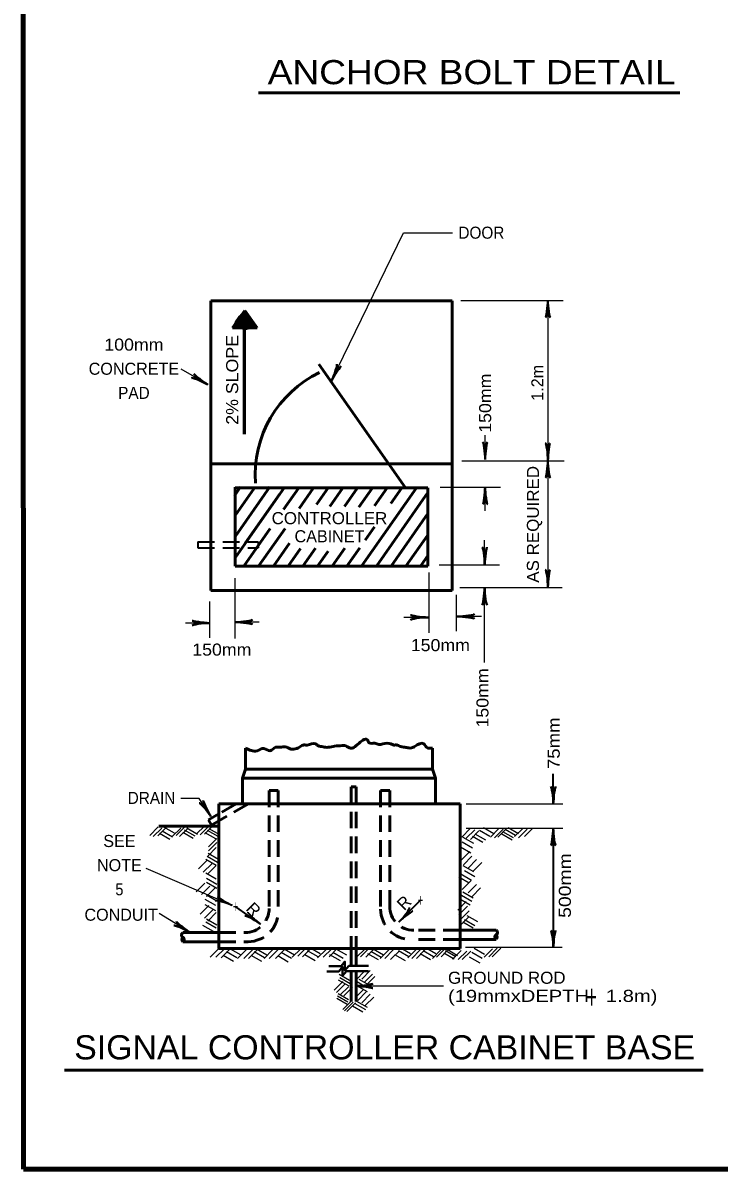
# Model space of a CAD drawing. Extents: x -711 to 145, y 25 to 569.
# Drawn here: x -653.6 to -515, y 36.6 to 264.5 of the extents above; entities that cross this region are included whole.
import ezdxf
from ezdxf.enums import TextEntityAlignment as Align

# ---------------------------------------------------------------- set-up
doc = ezdxf.new("R2010")
doc.units = 0
doc.header["$LTSCALE"] = 1.1
doc.linetypes.add('MEDIUM_DASHED', pattern=[4.5, 3, -1.5])
doc.layers.add('1', color=7, linetype='Continuous', lineweight=53)

msp = doc.modelspace()

# ---------------------------------------------------------------- linework, layer by layer
at = {"layer": '1'}
for p, q in [((-606.714, 250.622), (-522.826, 250.622)), ((-616.166, 209.253), (-616.166, 151.653)), ((-616.166, 209.253), (-609.079, 209.253)), ((-611.365, 209.253), (-611.365, 209.114)), ((-611.223, 209.253), (-568.166, 209.253)), ((-568.166, 209.253), (-568.166, 151.653)), ((-609.428, 207.33), (-611.866, 203.848)), ((-609.428, 207.33), (-606.991, 203.848)), ((-611.866, 203.848), (-606.991, 203.848)), ((-577.468, 172.049), (-594.676, 196.623)), ((-616.166, 176.853), (-568.166, 176.853)), ((-610.281, 172.228), (-611.499, 170.489)), ((-611.365, 172.188), (-611.365, 172.002)), ((-611.365, 172.053), (-611.223, 172.053)), ((-611.365, 172.053), (-572.966, 172.053)), ((-611.365, 172.053), (-611.365, 156.453)), ((-601.614, 172.053), (-611.365, 158.127)), ((-607.618, 171.847), (-611.343, 166.528)), ((-604.417, 172.235), (-611.299, 162.405)), ((-598.684, 172.053), (-601.698, 167.749)), ((-595.755, 172.053), (-598.616, 167.966)), ((-592.825, 172.053), (-595.165, 168.711)), ((-589.895, 172.053), (-592.48, 168.361)), ((-586.965, 172.053), (-589.567, 168.336)), ((-584.035, 172.053), (-586.751, 168.174)), ((-575.245, 172.053), (-586.169, 156.453)), ((-581.105, 172.053), (-583.598, 168.493)), ((-572.966, 171.125), (-583.239, 156.453)), ((-578.175, 172.053), (-580.339, 168.963)), ((-572.966, 172.053), (-572.966, 156.453)), ((-602.451, 170.859), (-609.333, 161.029)), ((-572.966, 166.941), (-580.309, 156.453)), ((-583.594, 164.314), (-585.461, 161.648)), ((-604.353, 163.957), (-609.608, 156.453)), ((-601.416, 163.967), (-606.678, 156.453)), ((-573.095, 162.572), (-577.379, 156.453)), ((-600.545, 161.027), (-603.748, 156.453)), ((-598.33, 160.007), (-600.818, 156.453)), ((-595.364, 160.057), (-597.888, 156.453)), ((-589.53, 160.021), (-592.028, 156.453)), ((-586.556, 160.084), (-589.099, 156.453)), ((-592.837, 159.482), (-594.958, 156.453)), ((-572.966, 158.572), (-574.371, 156.565)), ((-611.365, 156.453), (-572.966, 156.453)), ((-616.166, 151.653), (-568.166, 151.653)), ((-609.272, 116.072), (-609.272, 120.272)), ((-572.072, 116.072), (-572.072, 120.272)), ((-609.272, 116.072), (-609.901, 114.3)), ((-609.901, 114.3), (-571.501, 114.3)), ((-609.901, 114.3), (-609.901, 109.211)), ((-609.272, 116.072), (-572.072, 116.072)), ((-572.072, 116.072), (-571.501, 114.3)), ((-571.501, 114.3), (-571.501, 109.211)), ((-614.59, 107.207), (-616.676, 106.003)), ((-614.59, 109.211), (-566.59, 109.211)), ((-614.59, 109.211), (-614.59, 80.411)), ((-566.59, 109.211), (-566.59, 80.411)), ((-616.676, 106.003), (-616.076, 104.964)), ((-614.59, 105.822), (-616.076, 104.964)), ((-626.547, 104.789), (-614.547, 104.789)), ((-621.737, 83.595), (-614.537, 83.595)), ((-566.618, 84.053), (-559.418, 84.053)), ((-566.618, 82.252), (-559.418, 82.252)), ((-621.737, 81.795), (-614.537, 81.795)), ((-614.59, 80.411), (-566.59, 80.411)), ((-588.238, 80.416), (-588.238, 76.928)), ((-587.265, 80.501), (-587.265, 76.901)), ((-588.238, 75.87), (-588.238, 69.898)), ((-587.278, 75.898), (-587.278, 69.898)), ((-645.301, 56.213), (-518.171, 56.213))]:
    msp.add_line(p, q, dxfattribs=at)
at = {"layer": '1', "lineweight": 25}
for p, q in [((-566.442, 209.315), (-546.042, 209.315)), ((-616.795, 192.577), (-622.077, 195.644)), ((-561.593, 177.704), (-561.593, 182.504)), ((-566.255, 177.424), (-545.855, 177.424)), ((-570.545, 172.203), (-558.545, 172.203)), ((-561.593, 167.447), (-561.593, 172.247)), ((-561.686, 156.817), (-561.686, 161.617)), ((-572.783, 155.232), (-572.783, 143.232)), ((-570.731, 156.724), (-558.731, 156.724)), ((-611.387, 154.113), (-611.387, 142.113)), ((-567.374, 150.756), (-567.374, 143.556)), ((-566.628, 152.248), (-546.228, 152.248)), ((-561.686, 137.311), (-561.686, 152.199)), ((-616.422, 149.45), (-616.422, 142.25)), ((-572.969, 146.28), (-577.769, 146.28)), ((-562.339, 146.466), (-567.139, 146.466)), ((-616.422, 145.161), (-621.222, 145.161)), ((-606.538, 145.347), (-611.338, 145.347)), ((-565.351, 109.2), (-546.151, 109.2)), ((-617.385, 104.854), (-619.082, 103.157)), ((-615.784, 104.854), (-617.481, 103.157)), ((-626.648, 104.625), (-628.345, 102.928)), ((-625.961, 104.397), (-627.659, 102.699)), ((-625.047, 104.511), (-626.744, 102.814)), ((-624.36, 102.109), (-626.439, 103.309)), ((-623.789, 102.567), (-625.867, 103.767)), ((-623.446, 103.367), (-625.524, 104.567)), ((-622.188, 104.397), (-623.885, 102.699)), ((-621.387, 104.625), (-623.084, 102.928)), ((-620.701, 104.397), (-622.398, 102.699)), ((-619.672, 102.338), (-621.75, 103.538)), ((-619.329, 102.796), (-621.407, 103.996)), ((-618.871, 103.139), (-620.95, 104.339)), ((-616.584, 104.74), (-618.281, 103.043)), ((-615.212, 102.224), (-617.29, 103.424)), ((-614.754, 102.681), (-616.833, 103.881)), ((-614.411, 103.024), (-616.49, 104.224)), ((-564.551, 104.282), (-566.248, 102.585)), ((-565.351, 104.4), (-546.151, 104.4)), ((-563.636, 104.053), (-565.333, 102.356)), ((-562.835, 103.825), (-564.532, 102.128)), ((-562.035, 101.538), (-564.113, 102.738)), ((-561.463, 101.995), (-563.542, 103.195)), ((-560.663, 102.681), (-562.741, 103.881)), ((-559.862, 103.253), (-561.941, 104.453)), ((-558.833, 104.282), (-560.53, 102.585)), ((-558.032, 104.168), (-559.729, 102.471)), ((-557.346, 104.282), (-559.043, 102.585)), ((-556.202, 101.995), (-558.281, 103.195)), ((-555.974, 102.453), (-558.052, 103.653)), ((-555.516, 102.91), (-557.595, 104.11)), ((-554.945, 103.253), (-557.023, 104.453)), ((-554.03, 104.397), (-555.727, 102.699)), ((-553.229, 104.168), (-554.926, 102.471)), ((-552.086, 104.397), (-553.783, 102.699)), ((-615.097, 100.508), (-616.794, 98.811)), ((-614.983, 102.338), (-616.68, 100.641)), ((-614.983, 101.538), (-616.68, 99.841)), ((-564.436, 99.365), (-566.515, 100.565)), ((-564.093, 100.394), (-566.172, 101.594)), ((-563.865, 101.309), (-565.943, 102.509)), ((-615.097, 96.963), (-617.176, 98.163)), ((-614.869, 97.535), (-616.947, 98.735)), ((-614.64, 98.107), (-616.718, 99.307)), ((-564.665, 99.708), (-566.362, 98.011)), ((-564.208, 98.793), (-565.905, 97.096)), ((-563.293, 98.107), (-564.99, 96.41)), ((-611.944, 89.02), (-629.073, 96.336)), ((-616.927, 97.992), (-618.624, 96.295)), ((-616.012, 97.306), (-617.709, 95.609)), ((-615.097, 96.963), (-616.795, 95.266)), ((-563.865, 95.705), (-565.943, 96.905)), ((-563.636, 94.676), (-565.714, 95.876)), ((-562.264, 97.535), (-563.961, 95.838)), ((-615.097, 94.219), (-617.176, 95.419)), ((-614.983, 93.189), (-617.062, 94.389)), ((-614.983, 92.389), (-617.062, 93.589)), ((-564.779, 93.418), (-566.858, 94.618)), ((-564.322, 93.99), (-566.401, 95.19)), ((-564.436, 93.876), (-566.133, 92.178)), ((-617.385, 93.418), (-619.082, 91.721)), ((-616.355, 92.846), (-618.052, 91.149)), ((-615.326, 92.503), (-617.023, 90.806)), ((-563.979, 90.445), (-566.057, 91.645)), ((-563.293, 93.189), (-564.99, 91.492)), ((-562.492, 92.503), (-564.189, 90.806)), ((-616.584, 88.958), (-618.281, 87.261)), ((-615.212, 88.958), (-617.29, 90.158)), ((-615.212, 87.929), (-617.29, 89.129)), ((-614.983, 89.873), (-617.062, 91.073)), ((-565.351, 89.759), (-567.048, 88.062)), ((-564.551, 89.072), (-566.629, 90.272)), ((-564.208, 89.759), (-566.286, 90.959)), ((-620.33, 83.629), (-626.505, 87.403)), ((-615.784, 88.158), (-617.481, 86.461)), ((-615.097, 87.586), (-616.794, 85.889)), ((-565.122, 88.844), (-566.82, 87.147)), ((-564.779, 87.929), (-566.476, 86.232)), ((-564.779, 86.785), (-566.476, 85.088)), ((-563.064, 85.756), (-565.143, 86.956)), ((-615.669, 83.812), (-617.748, 85.012)), ((-615.097, 84.498), (-617.176, 85.698)), ((-614.983, 85.07), (-617.062, 86.27)), ((-563.979, 84.498), (-566.057, 85.698)), ((-563.636, 84.956), (-565.714, 86.156)), ((-614.64, 80.381), (-616.337, 78.684)), ((-613.496, 80.381), (-615.193, 78.684)), ((-612.467, 80.267), (-614.164, 78.57)), ((-610.18, 79.123), (-612.258, 80.323)), ((-609.151, 80.152), (-610.848, 78.455)), ((-607.893, 80.152), (-609.59, 78.455)), ((-606.978, 80.152), (-608.675, 78.455)), ((-605.034, 79.123), (-607.112, 80.323)), ((-603.89, 80.152), (-605.587, 78.455)), ((-602.861, 80.152), (-604.558, 78.455)), ((-601.603, 80.152), (-603.3, 78.455)), ((-599.545, 79.123), (-601.623, 80.323)), ((-598.287, 80.381), (-599.984, 78.684)), ((-597.143, 80.61), (-598.84, 78.913)), ((-596.228, 80.496), (-597.925, 78.798)), ((-594.856, 78.78), (-596.934, 79.98)), ((-594.398, 79.352), (-596.477, 80.552)), ((-593.255, 80.267), (-594.952, 78.57)), ((-592.111, 80.381), (-593.808, 78.684)), ((-590.968, 80.495), (-592.665, 78.798)), ((-589.138, 79.123), (-591.216, 80.323)), ((-585.478, 80.381), (-587.176, 78.684)), ((-584.678, 80.496), (-586.375, 78.798)), ((-583.649, 80.381), (-585.346, 78.684)), ((-582.276, 78.666), (-584.355, 79.866)), ((-581.819, 79.123), (-583.897, 80.323)), ((-580.79, 80.153), (-582.487, 78.455)), ((-579.875, 80.153), (-581.572, 78.455)), ((-578.731, 79.924), (-580.428, 78.227)), ((-576.787, 78.78), (-578.866, 79.98)), ((-576.444, 79.352), (-578.523, 80.552)), ((-575.3, 80.267), (-576.998, 78.57)), ((-574.5, 80.152), (-576.197, 78.455)), ((-573.585, 80.152), (-575.282, 78.455)), ((-571.87, 78.78), (-573.948, 79.98)), ((-571.412, 79.352), (-573.491, 80.552)), ((-570.383, 80.152), (-572.08, 78.455)), ((-569.582, 80.381), (-571.279, 78.684)), ((-568.668, 80.495), (-570.365, 78.798)), ((-567.41, 78.78), (-569.488, 79.98)), ((-567.067, 79.009), (-569.145, 80.209)), ((-566.38, 80.038), (-568.077, 78.341)), ((-565.237, 79.924), (-566.934, 78.227)), ((-564.436, 79.924), (-566.133, 78.227)), ((-565.466, 80.727), (-546.265, 80.727)), ((-561.692, 79.238), (-563.77, 80.438)), ((-560.091, 80.381), (-561.788, 78.684)), ((-559.176, 80.496), (-560.873, 78.798)), ((-558.49, 80.496), (-560.187, 78.798)), ((-611.667, 77.865), (-613.745, 79.065)), ((-610.981, 78.551), (-613.059, 79.751)), ((-606.063, 77.865), (-608.142, 79.065)), ((-605.491, 78.551), (-607.57, 79.751)), ((-600.803, 77.751), (-602.881, 78.951)), ((-600.116, 78.437), (-602.195, 79.637)), ((-595.428, 77.98), (-597.506, 79.18)), ((-590.396, 77.98), (-592.474, 79.18)), ((-589.824, 78.437), (-591.903, 79.637)), ((-582.848, 78.208), (-584.927, 79.408)), ((-577.473, 77.98), (-579.552, 79.18)), ((-572.442, 78.208), (-574.52, 79.408)), ((-567.753, 78.323), (-569.831, 79.523)), ((-562.607, 77.522), (-564.685, 78.722)), ((-562.149, 78.437), (-564.228, 79.637)), ((-588.566, 74.091), (-590.644, 75.291)), ((-585.593, 75.921), (-587.29, 74.224)), ((-584.449, 76.035), (-586.146, 74.338)), ((-583.992, 75.349), (-585.689, 73.652)), ((-589.938, 73.863), (-591.635, 72.166)), ((-589.481, 73.405), (-591.178, 71.708)), ((-588.68, 72.948), (-590.759, 74.148)), ((-588.452, 73.405), (-590.53, 74.605)), ((-587.394, 72.993), (-569.897, 72.993)), ((-585.135, 72.648), (-587.214, 73.848)), ((-585.021, 71.804), (-587.1, 73.004)), ((-584.563, 73.062), (-586.642, 74.262)), ((-583.534, 74.892), (-585.231, 73.195)), ((-588.909, 69.746), (-590.988, 70.946)), ((-588.795, 70.203), (-590.873, 71.403)), ((-588.795, 72.833), (-590.492, 71.136)), ((-587.994, 72.719), (-589.691, 71.022)), ((-585.707, 72.376), (-587.404, 70.679)), ((-585.25, 71.804), (-586.947, 70.107)), ((-584.449, 71.347), (-586.146, 69.65)), ((-583.763, 70.775), (-585.46, 69.078)), ((-589.024, 69.288), (-591.102, 70.488)), ((-588.223, 69.974), (-589.92, 68.277)), ((-587.88, 69.746), (-589.577, 68.049)), ((-587.422, 69.631), (-589.12, 67.934)), ((-585.936, 67.802), (-588.014, 69.002)), ((-585.364, 68.259), (-587.442, 69.459)), ((-585.021, 68.716), (-587.099, 69.916))]:
    msp.add_line(p, q, dxfattribs=at)
at = {"layer": '1', "lineweight": 60}
msp.add_line((-609.522, 206.704), (-609.522, 182.704), dxfattribs=at)
at = {"layer": '1', "linetype": 'MEDIUM_DASHED', "lineweight": 35}
for p, q in [((-618.753, 161.293), (-606.753, 161.293)), ((-618.753, 161.293), (-618.753, 160.093)), ((-618.753, 160.093), (-606.753, 160.093)), ((-606.753, 161.293), (-606.753, 160.093))]:
    msp.add_line(p, q, dxfattribs=at)
at = {"layer": '1', "lineweight": 35}
for p, q in [((-548.025, 109.174), (-548.025, 115.174)), ((-548.025, 104.37), (-548.025, 80.582)), ((-578.731, 85.756), (-574.489, 89.999)), ((-606.292, 85.299), (-611.207, 88.74))]:
    msp.add_line(p, q, dxfattribs=at)
at = {"layer": '1', "linetype": 'MEDIUM_DASHED'}
for p, q in [((-604.584, 111.87), (-604.584, 88.395)), ((-604.584, 111.87), (-602.784, 111.87)), ((-602.784, 111.87), (-602.784, 87.795)), ((-588.225, 112.593), (-587.265, 112.593)), ((-588.225, 112.593), (-588.225, 80.411)), ((-587.265, 112.593), (-587.265, 80.411)), ((-582.384, 111.87), (-582.384, 88.252)), ((-582.384, 111.87), (-580.584, 111.87)), ((-580.584, 111.87), (-580.584, 88.853)), ((-611.12, 109.211), (-614.59, 107.208)), ((-608.72, 109.211), (-614.59, 105.822)), ((-614.537, 83.595), (-609.384, 83.595)), ((-566.618, 82.252), (-576.384, 82.252)), ((-566.618, 84.053), (-575.784, 84.053)), ((-614.537, 81.795), (-608.784, 81.795))]:
    msp.add_line(p, q, dxfattribs=at)
at = {"layer": '1', "lineweight": 40}
for p, q in [((-588.726, 76.966), (-588.266, 76.966)), ((-588.238, 76.966), (-584.807, 76.966))]:
    msp.add_line(p, q, dxfattribs=at)
at = {"layer": '1', "lineweight": 158}
msp.add_line((138.105, 36.575), (-653.495, 36.575), dxfattribs=at)
msp.add_lwpolyline([(138.105, 562.675), (-653.595, 562.575), (-653.495, 36.575)], dxfattribs=at)
at = {"layer": '1', "lineweight": 25}
for points in [[(-592.178, 193.323), (-577.818, 222.789), (-568.119, 222.789)], [(-549.098, 209.362), (-549.098, 177.471), (-549.098, 152.292)], [(-616.212, 106.729), (-618.5, 110.275), (-622.188, 110.275)]]:
    msp.add_lwpolyline(points, dxfattribs=at)
at = {"layer": '1', "lineweight": 40}
for points in [[(-592.669, 76.928), (-590.269, 76.928), (-589.498, 77.847), (-589.498, 76.047), (-588.726, 76.966)], [(-593.126, 75.87), (-590.726, 75.87), (-589.955, 76.789), (-589.955, 74.989), (-589.184, 75.909), (-584.807, 75.909)]]:
    msp.add_lwpolyline(points, dxfattribs=at)
at = {"layer": '1'}
for centre, radius, start, end in [((-584.792, 174.622), 22.575, 115.56181, 184.16724), ((-621.427, 82.225), 0.518, 121.91368, 234.28887), ((-622.003, 82.225), 0.518, 305.71113, 58.08632), ((-559.146, 82.711), 0.518, 121.91368, 234.28887), ((-559.722, 82.711), 0.518, 305.71113, 58.08632)]:
    msp.add_arc(centre, radius, start, end, dxfattribs=at)
at = {"layer": '1', "linetype": 'MEDIUM_DASHED'}
for centre, radius, start, end in [((-609.384, 88.395), 4.8, 270, 0), ((-608.784, 87.795), 6, 270, 0), ((-576.384, 88.252), 6, 180, 270), ((-575.784, 88.853), 4.8, 180, 270)]:
    msp.add_arc(centre, radius, start, end, dxfattribs=at)
at = {"layer": '1', "lineweight": 40}
for centre, major_axis, ratio, start_param, end_param in [((-549.352, 208.017), (-0.211, -2.108), 0.07063, 6.2823074, 8.5597026), ((-549.352, 208.017), (-0.211, -2.108), 0.07063, 6.2823074, 8.5597026), ((-548.766, 208.052), (-0.187, 2.143), 0.122415, 0.8963533, 3.1415927), ((-548.766, 208.052), (-0.187, 2.143), 0.122415, 0.8963533, 3.1415927), ((-591.902, 194.646), (-0.77, -2.008), 0.122415, 0.8963533, 3.1415927), ((-591.361, 194.421), (1.113, 1.802), 0.07063, 6.2823074, 8.5597026), ((-618.094, 192.948), (1.947, -0.914), 0.122415, 0.8963533, 3.1415927), ((-617.83, 193.472), (1.717, -1.241), 0.07063, 3.1407148, 5.41811), ((-561.924, 179.013), (0.187, -2.143), 0.122415, 0.8963533, 3.1415927), ((-561.339, 179.049), (0.211, 2.108), 0.07063, 6.2823074, 8.5597026), ((-549.429, 178.781), (0.187, -2.143), 0.122415, 0.8963533, 3.1415927), ((-548.844, 178.816), (0.211, 2.108), 0.07063, 6.2823074, 8.5597026), ((-549.352, 176.127), (-0.211, -2.108), 0.07063, 6.2823074, 8.5597026), ((-548.766, 176.162), (-0.187, 2.143), 0.122415, 0.8963533, 3.1415927), ((-561.847, 170.902), (-0.211, -2.108), 0.07063, 6.2823074, 8.5597026), ((-561.261, 170.937), (-0.187, 2.143), 0.122415, 0.8963533, 3.1415927), ((-562.018, 158.126), (0.187, -2.143), 0.122415, 0.8963533, 3.1415927), ((-561.432, 158.161), (0.211, 2.108), 0.07063, 6.2823074, 8.5597026), ((-549.429, 153.601), (0.187, -2.143), 0.122415, 0.8963533, 3.1415927), ((-548.844, 153.637), (0.211, 2.108), 0.07063, 6.2823074, 8.5597026), ((-561.94, 150.854), (-0.211, -2.108), 0.07063, 6.2823074, 8.5597026), ((-561.355, 150.889), (-0.187, 2.143), 0.122415, 0.8963533, 3.1415927), ((-574.279, 145.948), (2.143, 0.187), 0.122415, 0.8963533, 3.1415927), ((-574.314, 146.534), (2.108, -0.211), 0.07063, 3.1407148, 5.41811), ((-565.794, 146.213), (2.108, -0.211), 0.07063, 6.2823074, 8.5597026), ((-565.829, 146.798), (-2.143, -0.187), 0.122415, 0.8963533, 3.1415927), ((-617.732, 144.829), (2.143, 0.187), 0.122415, 0.8963533, 3.1415927), ((-617.767, 145.415), (2.108, -0.211), 0.07063, 3.1407148, 5.41811), ((-610.029, 145.679), (-2.143, -0.187), 0.122415, 0.8963533, 3.1415927), ((-609.993, 145.094), (2.108, -0.211), 0.07063, 6.2823074, 8.5597026), ((-548.357, 110.483), (0.187, -2.143), 0.122415, 0.8963533, 3.1415927), ((-547.771, 110.518), (0.211, 2.108), 0.07063, 6.2823074, 8.5597026), ((-617.201, 107.65), (1.319, -1.699), 0.122415, 0.8963533, 3.1415927), ((-616.728, 107.997), (0.966, -1.885), 0.07063, 3.1407148, 5.41811), ((-548.279, 103.026), (-0.211, -2.108), 0.07063, 6.2823074, 8.5597026), ((-547.694, 103.061), (-0.187, 2.143), 0.122415, 0.8963533, 3.1415927), ((-621.62, 84.029), (1.926, -0.958), 0.122415, 0.8963533, 3.1415927), ((-621.344, 84.547), (-1.689, 1.279), 0.07063, 6.2823074, 8.5597026), ((-548.357, 81.892), (0.187, -2.143), 0.122415, 0.8963533, 3.1415927), ((-547.771, 81.927), (0.211, 2.108), 0.07063, 6.2823074, 8.5597026), ((-586.049, 72.739), (2.108, -0.211), 0.07063, 6.2823074, 8.5597026), ((-586.084, 73.325), (-2.143, -0.187), 0.122415, 0.8963533, 3.1415927)]:
    msp.add_ellipse(centre, major_axis=major_axis, ratio=ratio, start_param=start_param, end_param=end_param, dxfattribs=at)
at = {"layer": '1', "lineweight": 35}
for centre, major_axis, ratio, start_param, end_param in [((-613.278, 89.229), (2.044, -0.669), 0.122415, 0.8963533, 3.1415927), ((-613.081, 89.782), (-1.856, 1.022), 0.07063, 6.2823074, 8.5597026), ((-607.555, 85.778), (1.863, -1.076), 0.122415, 0.8963533, 3.1415927), ((-607.247, 86.278), (-1.606, 1.382), 0.07063, 6.2823074, 8.5597026), ((-578.04, 86.916), (-1.383, -1.648), 0.122415, 0.8963533, 3.1415927), ((-577.601, 86.527), (1.639, 1.341), 0.07063, 6.2823074, 8.5597026)]:
    msp.add_ellipse(centre, major_axis=major_axis, ratio=ratio, start_param=start_param, end_param=end_param, dxfattribs=at)
at = {"layer": '1'}
for centre, major_axis, start_param, end_param in [((-621.435, 83.175), (0.496, 0.357), 1.5707963, 3.6711132), ((-559.714, 83.661), (-0.496, 0.357), 2.6120721, 4.712389)]:
    msp.add_ellipse(centre, major_axis=major_axis, ratio=0.847055, start_param=start_param, end_param=end_param, dxfattribs=at)
for points in [[(-609.522, 206.611), (-609.522, 206.331), (-609.522, 206.89), (-609.429, 205.585), (-609.708, 205.585), (-609.708, 206.144), (-609.802, 206.238), (-610.175, 205.585), (-610.641, 204.839), (-610.734, 204.186), (-610.921, 204.186), (-611.107, 204.186), (-611.293, 204.093), (-610.921, 204.746), (-611.293, 204.186), (-609.895, 206.331), (-609.242, 205.678), (-608.962, 205.865), (-608.589, 205.305), (-608.496, 205.026), (-608.776, 205.492), (-609.429, 206.051), (-608.962, 206.238), (-608.776, 205.958), (-608.589, 205.119), (-608.403, 204.839), (-608.123, 204.28), (-607.937, 204.093), (-608.123, 204.932), (-608.496, 205.212), (-607.843, 204.373), (-607.75, 204.186), (-608.589, 204.373), (-609.335, 204.839), (-609.615, 205.212), (-609.802, 205.305), (-609.895, 204.932), (-609.988, 204.466), (-610.175, 204.373), (-610.175, 204.28), (-609.056, 205.305), (-610.081, 205.119), (-610.175, 204.373), (-609.708, 204.466), (-609.242, 204.466), (-608.776, 205.026), (-608.683, 204.932), (-609.335, 204.559), (-609.242, 204), (-608.962, 204), (-608.869, 204.653), (-610.361, 204.466), (-610.548, 203.813), (-610.175, 204.28), (-609.988, 204), (-608.403, 204.28), (-608.403, 204.559), (-608.776, 205.399), (-609.149, 205.678), (-609.056, 205.119), (-608.496, 205.119), (-609.522, 205.678), (-609.988, 205.399), (-609.335, 205.119), (-609.242, 206.424), (-608.496, 205.212), (-608.123, 204.559), (-607.843, 204.28), (-608.683, 204.839), (-609.522, 205.678), (-607.564, 203.907), (-608.403, 205.399), (-609.522, 205.492), (-609.522, 205.958), (-609.895, 204.466), (-609.988, 204.28)], [(-609.272, 120.272), (-606.985, 119.76), (-605.613, 120.218), (-604.355, 119.76), (-603.326, 120.447), (-602.411, 120.447), (-601.382, 120.561), (-600.238, 120.104), (-599.095, 120.218), (-598.752, 120.332), (-597.837, 120.904), (-597.036, 120.904), (-595.321, 121.133), (-594.864, 120.79), (-593.835, 120.561), (-593.377, 120.447), (-592.805, 120.447), (-591.547, 120.675), (-590.061, 120.79), (-589.603, 120.79), (-588.574, 120.332), (-587.888, 120.332), (-587.545, 120.561), (-586.973, 121.018), (-585.029, 121.933), (-584.686, 121.361), (-583.543, 121.247), (-582.742, 121.018), (-581.942, 121.133), (-580.341, 121.133), (-579.769, 120.904), (-579.083, 120.904), (-578.625, 120.675), (-577.596, 120.447), (-576.796, 120.332), (-576.224, 120.332), (-575.538, 120.675), (-573.823, 121.133), (-573.251, 120.447), (-572.072, 120.272)]]:
    msp.add_spline(points, degree=3, dxfattribs=at)

# ---------------------------------------------------------------- texts
for s, height, width, p in [('ANCHOR BOLT DETAIL', 4.8, 1.15, (-604.872, 252.314)), ('GROUND ROD', 2.4, 1.05, (-568.982, 73.422)), ('(19mmxDEPTH   1.8m)', 2.4, 1.25, (-568.982, 69.822)), ('+', 4.8, 0.55, (-541.439, 68.443)), ('SIGNAL CONTROLLER CABINET BASE', 4.8, 1.05, (-643.385, 58.388))]:
    msp.add_text(s, height=height, dxfattribs=dict(at, width=width)).set_placement(p)
for s, width, p in [('DOOR', 0.95, (-562.339, 221.589)), ('100mm', 1.1, (-631.499, 199.33)), ('PAD', 0.95, (-631.499, 189.73)), ('CONTROLLER', 1.05, (-592.574, 164.816)), ('150mm', 1.1, (-570.497, 139.568)), ('150mm', 1.1, (-613.998, 138.68)), ('DRAIN', 0.95, (-627.992, 109.189)), ('5', 0.9, (-634.39, 91.016)), ('+', 0.55, (-611.281, 87.587)), ('+', 0.55, (-574.485, 88.874))]:
    msp.add_text(s, height=2.4, dxfattribs=dict(at, width=width)).set_placement(p, align=Align.CENTER)
for s, width, p in [('2% SLOPE', 1.1, (-610.746, 193.519)), ('150mm', 1.1, (-560.39, 188.88)), ('AS REQUIRED', 1.05, (-550.882, 164.79)), ('150mm', 1.1, (-560.923, 130.272))]:
    msp.add_text(s, height=2.4, rotation=90, dxfattribs=dict(at, width=width)).set_placement(p, align=Align.CENTER)
for s, p in [('CONCRETE', (-631.499, 194.53)), ('CABINET', (-592.574, 161.216)), ('SEE', (-634.39, 100.616)), ('NOTE', (-634.39, 95.816))]:
    msp.add_text(s, height=2.4, dxfattribs=at).set_placement(p, align=Align.CENTER)
for s, rotation, p in [('1.2m', 90, (-549.994, 192.933)), ('R', 315, (-608.538, 87.365)), ('R', 45, (-576.879, 88.687))]:
    msp.add_text(s, height=2.4, rotation=rotation, dxfattribs=at).set_placement(p, align=Align.CENTER)
for s, width, p in [('75mm', 1.15, (-546.74, 116.125)), ('500mm', 1.2, (-544.525, 86.533))]:
    msp.add_text(s, height=2.4, rotation=90, dxfattribs=dict(at, width=width)).set_placement(p)
msp.add_text('CONDUIT', height=2.4, dxfattribs=at).set_placement((-641.345, 85.956))

doc.saveas('drawing.dxf')
